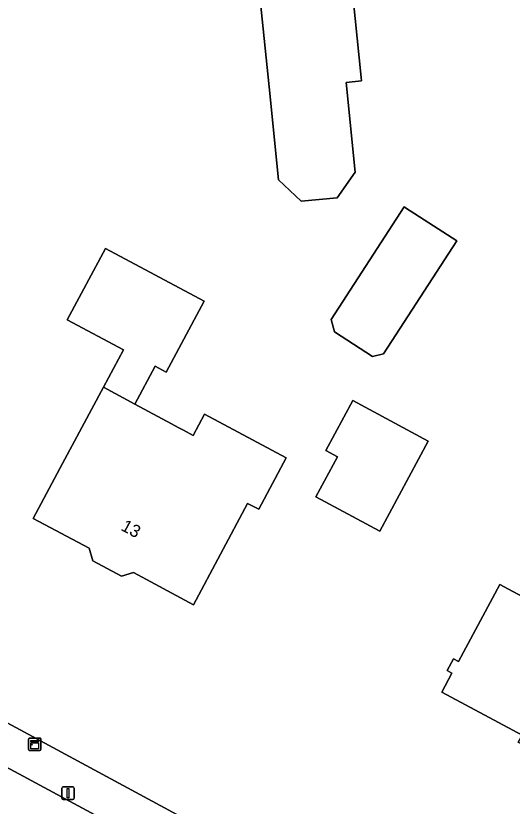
# Model space of a CAD drawing. Extents: x 161258 to 161838, y 380833 to 381727.
# Drawn here: x 161615.9 to 161655.9, y 381091.2 to 381154.9 of the extents above; entities that cross this region are included whole.
import ezdxf

# ---------------------------------------------------------------- set-up
doc = ezdxf.new("R2010")
doc.units = 0
for name, color, linetype in [('IMGEO_Erf', 7, 'Continuous'), ('IMGEO_Kast', 7, 'Continuous'), ('IMGEO_Lichtmast', 7, 'Continuous'), ('IMGEO_Pand', 7, 'Continuous'), ('IMGEO_Pand_nummerreeks', 7, 'Continuous'), ('IMGEO_Rijbaan_lokaal_open', 7, 'Continuous'), ('IMGEO_Voetpad_open', 7, 'Continuous')]:
    doc.layers.add(name, color=color, linetype=linetype)

msp = doc.modelspace()

# ---------------------------------------------------------------- linework, layer by layer
at = {"layer": 'IMGEO_Erf'}
for points in [[(161642.48, 381162.61), (161643.772, 381149.921), (161643.799, 381149.653), (161642.554, 381149.527), (161643.293, 381142.292), (161641.821, 381140.244), (161638.932, 381139.97), (161637.102, 381141.685), (161636.339, 381149.163), (161635.039, 381161.925)], [(161599.292, 381107.15), (161603.367, 381104.463), (161608.252, 381101.703), (161676.825, 381064.703), (161683.729, 381060.833), (161686.794, 381059.495), (161691.724, 381057.608), (161696.114, 381056.287), (161709.767, 381053.57)]]:
    msp.add_lwpolyline(points, dxfattribs=at)
for points in [[(161645.576, 381127.671), (161644.668, 381127.456), (161641.623, 381129.433), (161641.334, 381130.425), (161647.232, 381139.509), (161647.349, 381139.433), (161651.472, 381136.755)], [(161628.053, 381126.195), (161627.173, 381126.667), (161625.535, 381123.609), (161628.478, 381122.033), (161629.005, 381121.75), (161629.456, 381121.509), (161630.232, 381121.093), (161631.15, 381122.808), (161637.721, 381119.288), (161635.505, 381115.148), (161634.613, 381115.626), (161630.241, 381107.461), (161625.408, 381110.049), (161624.458, 381109.762), (161622.137, 381111.004), (161621.833, 381112.011), (161617.336, 381114.419), (161619.696, 381118.827), (161622.988, 381124.974), (161624.602, 381127.986), (161620.079, 381130.409), (161623.161, 381136.163), (161631.111, 381131.904)], [(161649.165, 381120.625), (161645.263, 381113.376), (161640.111, 381116.149), (161641.846, 381119.373), (161640.917, 381119.874), (161643.084, 381123.899)], [(161665.322, 381103.509), (161663.01, 381099.191), (161660.649, 381094.783), (161658.583, 381095.89), (161658.309, 381095.378), (161656.425, 381096.386), (161656.736, 381096.967), (161650.259, 381100.435), (161651.075, 381101.959), (161650.701, 381102.159), (161651.21, 381103.11), (161651.598, 381102.902), (161654.932, 381109.096)]]:
    msp.add_lwpolyline(points, close=True, dxfattribs=at)
at = {"layer": 'IMGEO_Kast'}
for p, q in [((161616.956, 381095.808), (161616.956, 381096.649)), ((161616.956, 381096.649), (161616.956, 381095.808)), ((161617.031, 381096.733), (161617.872, 381096.733)), ((161617.872, 381096.733), (161617.031, 381096.733)), ((161617.956, 381096.658), (161617.956, 381095.817)), ((161617.956, 381095.817), (161617.956, 381096.658)), ((161617.881, 381095.733), (161617.04, 381095.733)), ((161617.04, 381095.733), (161617.881, 381095.733))]:
    msp.add_line(p, q, dxfattribs=at)
for points in [[(161617.151, 381096.523), (161617.751, 381096.523), (161617.751, 381096.438), (161617.151, 381096.438), (161617.151, 381096.523)], [(161617.151, 381096.348), (161617.751, 381096.348), (161617.751, 381095.859), (161617.151, 381095.859), (161617.151, 381096.348)]]:
    msp.add_lwpolyline(points, dxfattribs=at)
msp.add_circle((161617.235, 381096.197), 0.0377, dxfattribs=at)
for centre, start, end in [((161617.034, 381096.655), 92.4484, 184.28452), ((161617.034, 381096.655), 92.4484, 184.28452), ((161617.878, 381096.655), 2.4484, 94.28452), ((161617.878, 381096.655), 2.4484, 94.28452), ((161617.034, 381095.811), 182.4484, 274.28452), ((161617.034, 381095.811), 182.4484, 274.28452), ((161617.878, 381095.811), 272.4484, 4.28452), ((161617.878, 381095.811), 272.4484, 4.28452)]:
    msp.add_arc(centre, 0.0779, start, end, dxfattribs=at)
at = {"layer": 'IMGEO_Lichtmast'}
for p, q in [((161619.64, 381091.888), (161619.64, 381092.688)), ((161619.64, 381092.688), (161619.64, 381091.888)), ((161619.74, 381092.788), (161620.53, 381092.788)), ((161620.53, 381092.788), (161619.74, 381092.788)), ((161620.63, 381092.688), (161620.63, 381091.888)), ((161620.63, 381091.888), (161620.63, 381092.688)), ((161620.53, 381091.788), (161619.74, 381091.788)), ((161619.74, 381091.788), (161620.53, 381091.788))]:
    msp.add_line(p, q, dxfattribs=at)
msp.add_lwpolyline([(161620.06, 381092.663), (161620.21, 381092.663), (161620.21, 381091.913), (161620.06, 381091.913), (161620.06, 381092.663)], dxfattribs=at)
for centre, start, end in [((161619.74, 381092.688), 90, 180), ((161619.74, 381092.688), 90, 180), ((161620.53, 381092.688), 0, 90), ((161620.53, 381092.688), 360, 90), ((161619.74, 381091.888), 180, 270), ((161619.74, 381091.888), 180, 270), ((161620.53, 381091.888), 270, 0), ((161620.53, 381091.888), 270, 0)]:
    msp.add_arc(centre, 0.1, start, end, dxfattribs=at)
at = {"layer": 'IMGEO_Pand'}
for points in [[(161642.48, 381162.61), (161635.039, 381161.925), (161636.339, 381149.163), (161637.102, 381141.685), (161638.932, 381139.97), (161641.821, 381140.244), (161643.293, 381142.292), (161642.554, 381149.527), (161643.799, 381149.653), (161643.772, 381149.921)], [(161641.334, 381130.425), (161641.623, 381129.433), (161644.668, 381127.456), (161645.576, 381127.671), (161651.472, 381136.755), (161647.349, 381139.433), (161647.232, 381139.509)], [(161622.988, 381124.974), (161625.535, 381123.609), (161627.173, 381126.667), (161628.053, 381126.195), (161631.111, 381131.904), (161623.161, 381136.163), (161620.079, 381130.409), (161624.602, 381127.986)], [(161637.721, 381119.288), (161631.15, 381122.808), (161630.232, 381121.093), (161629.456, 381121.509), (161629.005, 381121.75), (161628.478, 381122.033), (161625.535, 381123.609), (161622.988, 381124.974), (161619.696, 381118.827), (161617.336, 381114.419), (161621.833, 381112.011), (161622.137, 381111.004), (161624.458, 381109.762), (161625.408, 381110.049), (161630.241, 381107.461), (161634.613, 381115.626), (161635.505, 381115.148)], [(161649.165, 381120.625), (161643.084, 381123.899), (161640.917, 381119.874), (161641.846, 381119.373), (161640.111, 381116.149), (161645.263, 381113.376)], [(161663.01, 381099.191), (161665.322, 381103.509), (161654.932, 381109.096), (161651.598, 381102.902), (161651.21, 381103.11), (161650.701, 381102.159), (161651.075, 381101.959), (161650.259, 381100.435), (161656.736, 381096.967), (161656.425, 381096.386), (161658.309, 381095.378), (161658.583, 381095.89), (161660.649, 381094.783)]]:
    msp.add_lwpolyline(points, close=True, dxfattribs=at)
at = {"layer": 'IMGEO_Rijbaan_lokaal_open'}
msp.add_lwpolyline([(161622.315, 381078.834), (161623.675, 381078.64), (161630.283, 381077.643), (161631.678, 381077.263), (161632.244, 381076.986), (161635.58, 381083.294), (161623.338, 381089.989), (161611.018, 381096.621), (161607.745, 381090.263), (161608.262, 381090.01), (161609.367, 381089.192)], dxfattribs=at)
at = {"layer": 'IMGEO_Voetpad_open'}
msp.add_lwpolyline([(161598.405, 381103.885), (161602.607, 381101.294), (161602.851, 381101.158), (161607.838, 381098.385), (161610.746, 381096.768), (161611.018, 381096.621), (161623.338, 381089.989), (161635.58, 381083.294), (161638.009, 381081.966), (161651.628, 381074.813), (161654.689, 381073.206), (161664.516, 381067.867), (161669.88, 381065.045), (161677.177, 381060.856), (161680.698, 381058.941), (161685.459, 381056.689), (161686.794, 381059.495), (161683.729, 381060.833), (161676.825, 381064.703), (161608.252, 381101.703)], dxfattribs=at)

# ---------------------------------------------------------------- texts
at = {"layer": 'IMGEO_Pand_nummerreeks'}
msp.add_text('13', height=1, rotation=331.66724, dxfattribs=at).set_placement((161624.337, 381113.507))

doc.saveas('drawing.dxf')
